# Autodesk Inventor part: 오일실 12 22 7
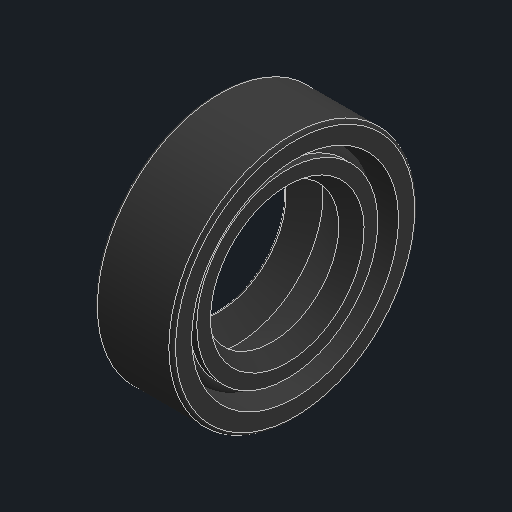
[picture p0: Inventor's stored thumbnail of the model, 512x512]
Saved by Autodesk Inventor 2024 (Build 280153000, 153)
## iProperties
Created: 2024-05
Part Number: 오일실 12 22 7
Material: 고무
Description: 오일-실
Document SubType Name: Modeling
Designer: kh_501
Density: 0.93 g/cm^3
Appearance: 기본값
Author: jhkim
Sending System: Autodesk Inventor 2025
Preprocessor: ST-DEVELOPER v20
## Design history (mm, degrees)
feature "Solid1"
node "솔리드1"
